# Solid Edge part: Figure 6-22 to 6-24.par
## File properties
Author: CADCIM
Template: Normal.par
Last saved by: TIET
Revision: 3
Application: Solid Edge
Accuracy: 0.99
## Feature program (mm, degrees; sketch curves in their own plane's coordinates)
sketch for "unnamed Protrusion 1" plane through (0, 0, 0) normal (0, -1, 0) x-axis (1, 0, 0)
  line (-47.9688, 40.4319) -> (-47.9688, 0)
  line (-47.9688, 0) -> (40.7735, 0)
  line (40.7735, 0) -> (11.4256, 32.2563)
  arc centre (-7.0661, 15.4319) radius 25 from (11.4256, 32.2563) to (-7.0661, 40.4319) ccw
  line (-7.0661, 40.4319) -> (-47.9688, 40.4319)
extrude "unnamed Protrusion 1" add finite 57.15 symmetric
sketch for "ExtrudedProtrusion_3" plane through (18.5879, 0, 24.3842) normal (0.739666, 0, 0.672975) x-axis (0, 1, 0)
  circle centre (0, -8.0136) radius 16.4586
extrude "ExtrudedProtrusion_3" add finite 41.275 along +normal
fillet "Round_5" radius 10
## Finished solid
Body 1: solid body, 12 faces, 26 edges, 16 vertices.
  Faces by surface: plane 8, cylinder 2, blend 1, torus 1
  Edges by curve: line 15, circle 8, intersection 3
Bounding box of the edges (mm; curved faces can reach further): 113.556 x 57.150 x 58.408, from (-47.9688, -28.575, 0) to (65.5868, 28.575, 58.4077).
Cylindrical faces by radius (mm): R16.4586 x1, R25 x1
Toroidal faces (ring radius, tube radius in mm): R26.4586 r10 x1
Planar faces by outward normal: +y 1, +z 1, -x 1, -y 1, -z 1, oblique 3
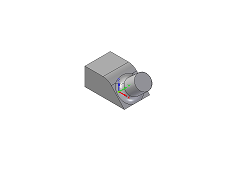
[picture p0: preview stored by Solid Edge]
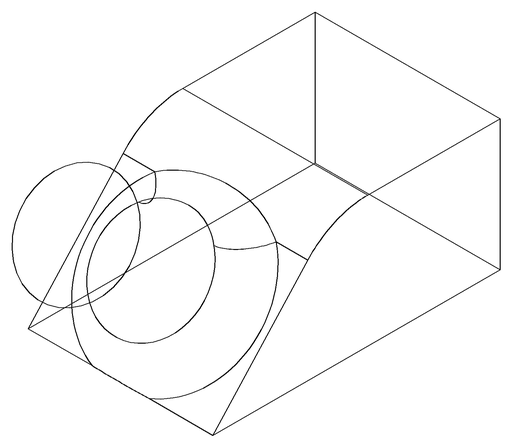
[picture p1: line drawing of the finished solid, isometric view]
